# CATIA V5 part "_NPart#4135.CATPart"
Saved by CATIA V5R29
Part number: evaparat? 2
Revision: HERHANG?
Definition: B??MEYEN
Nomenclature: evaparat? 2
Source: Unknown
Bounding box of the stored display mesh (mm): x -47.577 to 809.625, y -15.875 to 142.875, z -15.875 to 460.375
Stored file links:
  C:\Users\제5강의실-27\Desktop\가치같이_내작업\_NPart#4135.CATPart
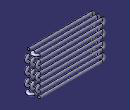
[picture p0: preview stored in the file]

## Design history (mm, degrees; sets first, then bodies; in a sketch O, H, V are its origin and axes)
Body1 "??k1" (main body)
  Solid1: solid without history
